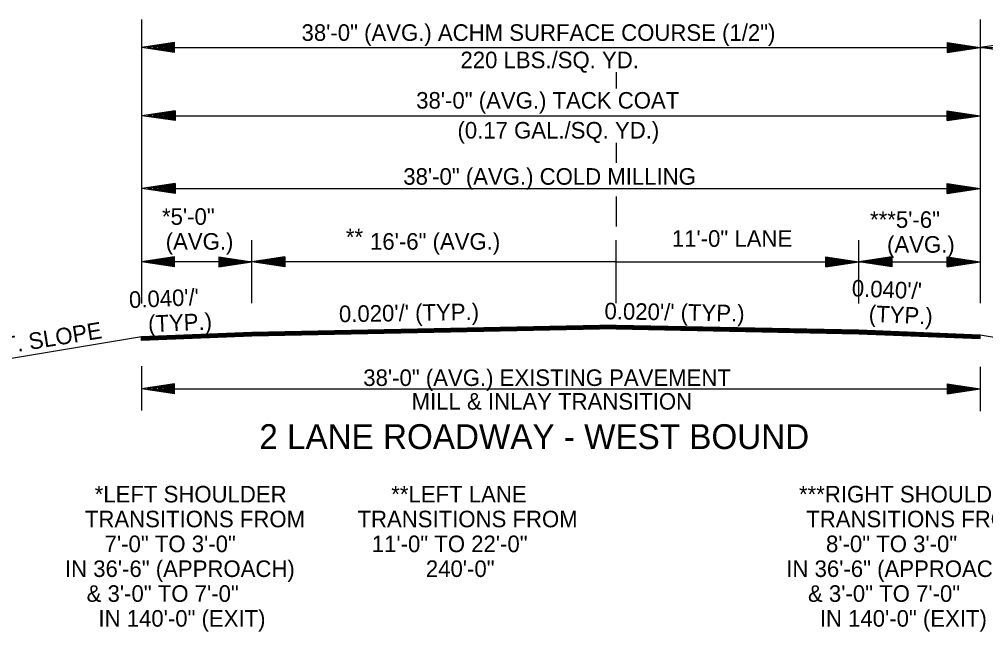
# Model space of a CAD drawing. Extents: x 542112 to 1930787, y -1968972 to 596640.
# Drawn here: x 544342.8 to 544780.6, y -1951874.4 to -1951597.2 of the extents above; entities that cross this region are included whole.
import ezdxf

# ---------------------------------------------------------------- set-up
doc = ezdxf.new("R2010")
doc.units = 0
doc.layers.add('R_Draft', color=7, linetype='Continuous')

msp = doc.modelspace()

# ---------------------------------------------------------------- linework, layer by layer
at = {"layer": 'R_Draft'}
for p, q in [((544398.18, -1951597.18), (544398.18, -1951725.86)), ((544778.18, -1951597.18), (544778.18, -1951725.69)), ((544413.18, -1951607.68), (544398.18, -1951609.93)), ((544413.18, -1951608.06), (544400.68, -1951609.93)), ((544413.18, -1951612.18), (544413.18, -1951607.68)), ((544763.18, -1951607.68), (544778.18, -1951609.93)), ((544763.18, -1951607.68), (544763.18, -1951612.18)), ((544763.18, -1951608.06), (544775.67, -1951609.93)), ((544793.18, -1951607.68), (544778.18, -1951609.93)), ((544793.18, -1951607.68), (544778.18, -1951609.93)), ((544413.18, -1951612.18), (544398.18, -1951609.93)), ((544413.18, -1951611.81), (544400.68, -1951609.93)), ((544413.18, -1951608.44), (544403.26, -1951609.93)), ((544413.18, -1951611.43), (544403.26, -1951609.93)), ((544413.18, -1951608.82), (544405.76, -1951609.93)), ((544413.18, -1951611.05), (544405.76, -1951609.93)), ((544408.18, -1951609.93), (544778.18, -1951609.93)), ((544413.18, -1951609.2), (544408.3, -1951609.93)), ((544413.18, -1951610.66), (544408.3, -1951609.93)), ((544413.18, -1951609.58), (544410.81, -1951609.93)), ((544413.18, -1951610.29), (544410.81, -1951609.93)), ((544763.18, -1951608.44), (544773.09, -1951609.93)), ((544763.18, -1951608.82), (544770.6, -1951609.93)), ((544763.18, -1951609.21), (544768.05, -1951609.93)), ((544763.18, -1951609.58), (544765.55, -1951609.93)), ((544763.18, -1951612.18), (544778.18, -1951609.93)), ((544763.18, -1951610.67), (544768.05, -1951609.93)), ((544763.18, -1951611.43), (544773.09, -1951609.93)), ((544763.18, -1951611.81), (544775.67, -1951609.93)), ((544763.18, -1951611.05), (544770.6, -1951609.93)), ((544763.18, -1951610.29), (544765.55, -1951609.93)), ((544778.18, -1951609.93), (545048.18, -1951609.93)), ((544793.18, -1951612.18), (544778.18, -1951609.93)), ((544793.18, -1951612.18), (544778.18, -1951609.93)), ((544613.18, -1951621.16), (544613.18, -1951628.53)), ((544413.38, -1951638.55), (544398.38, -1951640.8)), ((544413.38, -1951638.93), (544400.88, -1951640.8)), ((544413.38, -1951638.55), (544413.38, -1951643.05)), ((544763.18, -1951638.55), (544778.18, -1951640.8)), ((544763.18, -1951643.05), (544763.18, -1951638.55)), ((544763.18, -1951638.93), (544775.67, -1951640.8)), ((544413.38, -1951643.05), (544398.38, -1951640.8)), ((544413.38, -1951642.68), (544400.88, -1951640.8)), ((544413.38, -1951639.31), (544403.46, -1951640.8)), ((544413.38, -1951642.29), (544403.46, -1951640.8)), ((544413.38, -1951639.68), (544405.96, -1951640.8)), ((544413.38, -1951641.92), (544405.96, -1951640.8)), ((544408.18, -1951640.8), (544778.18, -1951640.8)), ((544413.38, -1951640.07), (544408.5, -1951640.8)), ((544413.38, -1951641.54), (544408.5, -1951640.8)), ((544413.38, -1951640.45), (544411.01, -1951640.8)), ((544413.38, -1951641.15), (544411.01, -1951640.8)), ((544763.18, -1951639.31), (544773.09, -1951640.8)), ((544763.18, -1951639.68), (544770.6, -1951640.8)), ((544763.18, -1951640.07), (544768.05, -1951640.8)), ((544763.18, -1951640.45), (544765.55, -1951640.8)), ((544763.18, -1951643.05), (544778.18, -1951640.8)), ((544763.18, -1951641.53), (544768.05, -1951640.8)), ((544763.18, -1951642.29), (544773.09, -1951640.8)), ((544763.18, -1951642.68), (544775.67, -1951640.8)), ((544763.18, -1951641.92), (544770.6, -1951640.8)), ((544763.18, -1951641.15), (544765.55, -1951640.8)), ((544613.18, -1951653.15), (544613.18, -1951662.11)), ((544413.38, -1951671.48), (544398.38, -1951673.73)), ((544413.38, -1951675.98), (544398.38, -1951673.73)), ((544413.38, -1951671.86), (544400.88, -1951673.73)), ((544413.38, -1951675.61), (544400.88, -1951673.73)), ((544413.38, -1951672.24), (544403.46, -1951673.73)), ((544413.38, -1951675.22), (544403.46, -1951673.73)), ((544413.38, -1951672.61), (544405.96, -1951673.73)), ((544413.38, -1951674.85), (544405.96, -1951673.73)), ((544408.18, -1951673.73), (544778.18, -1951673.73)), ((544413.38, -1951673), (544408.5, -1951673.73)), ((544413.38, -1951674.47), (544408.5, -1951673.73)), ((544413.38, -1951673.38), (544411.01, -1951673.73)), ((544413.38, -1951674.08), (544411.01, -1951673.73)), ((544413.38, -1951671.48), (544413.38, -1951675.98)), ((544763.18, -1951671.48), (544778.18, -1951673.73)), ((544763.18, -1951675.98), (544763.18, -1951671.48)), ((544763.18, -1951671.86), (544775.67, -1951673.73)), ((544763.18, -1951672.24), (544773.09, -1951673.73)), ((544763.18, -1951672.61), (544770.6, -1951673.73)), ((544763.18, -1951673), (544768.05, -1951673.73)), ((544763.18, -1951673.38), (544765.55, -1951673.73)), ((544763.18, -1951675.98), (544778.18, -1951673.73)), ((544763.18, -1951674.46), (544768.05, -1951673.73)), ((544763.18, -1951675.22), (544773.09, -1951673.73)), ((544763.18, -1951675.61), (544775.67, -1951673.73)), ((544763.18, -1951674.85), (544770.6, -1951673.73)), ((544763.18, -1951674.08), (544765.55, -1951673.73)), ((544613.18, -1951677.36), (544613.18, -1951691)), ((544448.18, -1951725.69), (544448.18, -1951697.13)), ((544613.18, -1951725.69), (544613.18, -1951697.13)), ((544723.18, -1951725.86), (544723.18, -1951697.13)), ((544413.18, -1951704.78), (544398.18, -1951707.03)), ((544448.18, -1951707.03), (544398.18, -1951707.03)), ((544413.18, -1951709.28), (544398.18, -1951707.03)), ((544413.18, -1951705.15), (544400.68, -1951707.03)), ((544413.18, -1951708.9), (544400.68, -1951707.03)), ((544413.18, -1951705.53), (544403.26, -1951707.03)), ((544413.18, -1951708.52), (544403.26, -1951707.03)), ((544413.18, -1951705.91), (544405.76, -1951707.03)), ((544413.18, -1951708.14), (544405.76, -1951707.03)), ((544413.18, -1951706.29), (544408.3, -1951707.03)), ((544413.18, -1951707.75), (544408.3, -1951707.03)), ((544413.18, -1951706.67), (544410.81, -1951707.03)), ((544413.18, -1951707.38), (544410.81, -1951707.03)), ((544413.18, -1951709.28), (544413.18, -1951704.78)), ((544433.18, -1951704.78), (544448.18, -1951707.03)), ((544433.18, -1951704.78), (544433.18, -1951709.28)), ((544433.18, -1951705.15), (544445.67, -1951707.03)), ((544433.18, -1951705.53), (544443.09, -1951707.03)), ((544433.18, -1951705.91), (544440.6, -1951707.03)), ((544433.18, -1951706.3), (544438.05, -1951707.03)), ((544433.18, -1951706.67), (544435.55, -1951707.03)), ((544433.18, -1951709.28), (544448.18, -1951707.03)), ((544433.18, -1951707.76), (544438.05, -1951707.03)), ((544433.18, -1951708.52), (544443.09, -1951707.03)), ((544433.18, -1951708.9), (544445.67, -1951707.03)), ((544433.18, -1951708.14), (544440.6, -1951707.03)), ((544433.18, -1951707.38), (544435.55, -1951707.03)), ((544463.18, -1951704.78), (544448.18, -1951707.03)), ((544613.18, -1951707.03), (544448.18, -1951707.03)), ((544463.18, -1951709.28), (544448.18, -1951707.03)), ((544463.18, -1951705.15), (544450.68, -1951707.03)), ((544463.18, -1951708.9), (544450.68, -1951707.03)), ((544463.18, -1951705.53), (544453.26, -1951707.03)), ((544463.18, -1951708.52), (544453.26, -1951707.03)), ((544463.18, -1951705.91), (544455.76, -1951707.03)), ((544463.18, -1951708.14), (544455.76, -1951707.03)), ((544463.18, -1951706.3), (544458.3, -1951707.03)), ((544463.18, -1951707.76), (544458.3, -1951707.03)), ((544463.18, -1951706.67), (544460.81, -1951707.03)), ((544463.18, -1951707.38), (544460.81, -1951707.03)), ((544463.18, -1951704.78), (544463.18, -1951709.28)), ((544613.18, -1951707.03), (544723.18, -1951707.03)), ((544708.18, -1951704.78), (544723.18, -1951707.03)), ((544708.18, -1951709.28), (544708.18, -1951704.78)), ((544708.18, -1951705.15), (544720.67, -1951707.03)), ((544708.18, -1951705.53), (544718.09, -1951707.03)), ((544708.18, -1951705.91), (544715.6, -1951707.03)), ((544708.18, -1951706.29), (544713.05, -1951707.03)), ((544708.18, -1951706.67), (544710.55, -1951707.03)), ((544708.18, -1951709.28), (544723.18, -1951707.03)), ((544708.18, -1951707.75), (544713.05, -1951707.03)), ((544708.18, -1951708.52), (544718.09, -1951707.03)), ((544708.18, -1951708.9), (544720.67, -1951707.03)), ((544708.18, -1951708.14), (544715.6, -1951707.03)), ((544708.18, -1951707.38), (544710.55, -1951707.03)), ((544738.18, -1951704.78), (544723.18, -1951707.03)), ((544723.18, -1951707.03), (544778.18, -1951707.03)), ((544738.18, -1951709.28), (544723.18, -1951707.03)), ((544738.18, -1951705.15), (544725.68, -1951707.03)), ((544738.18, -1951708.9), (544725.68, -1951707.03)), ((544738.18, -1951705.53), (544728.26, -1951707.03)), ((544738.18, -1951708.52), (544728.26, -1951707.03)), ((544738.18, -1951705.91), (544730.76, -1951707.03)), ((544738.18, -1951708.14), (544730.76, -1951707.03)), ((544738.18, -1951706.3), (544733.3, -1951707.03)), ((544738.18, -1951707.76), (544733.3, -1951707.03)), ((544738.18, -1951706.67), (544735.81, -1951707.03)), ((544738.18, -1951707.38), (544735.81, -1951707.03)), ((544738.18, -1951704.78), (544738.18, -1951709.28)), ((544763.18, -1951704.78), (544778.18, -1951707.03)), ((544763.18, -1951709.28), (544763.18, -1951704.78)), ((544763.18, -1951705.15), (544775.67, -1951707.03)), ((544763.18, -1951705.53), (544773.09, -1951707.03)), ((544763.18, -1951705.91), (544770.6, -1951707.03)), ((544763.18, -1951706.29), (544768.05, -1951707.03)), ((544763.18, -1951706.67), (544765.55, -1951707.03)), ((544763.18, -1951709.28), (544778.18, -1951707.03)), ((544763.18, -1951707.75), (544768.05, -1951707.03)), ((544763.18, -1951708.52), (544773.09, -1951707.03)), ((544763.18, -1951708.9), (544775.67, -1951707.03)), ((544763.18, -1951708.14), (544770.6, -1951707.03)), ((544763.18, -1951707.38), (544765.55, -1951707.03)), ((544448.18, -1951738.93), (544398.18, -1951740.93)), ((544448.18, -1951739.23), (544398.18, -1951741.23)), ((544448.18, -1951739.53), (544398.18, -1951741.53)), ((544613.18, -1951735.63), (544448.18, -1951738.93)), ((544613.18, -1951735.93), (544448.18, -1951739.23)), ((544613.18, -1951736.23), (544448.18, -1951739.53)), ((544613.18, -1951736.53), (544448.18, -1951739.83)), ((544613.18, -1951736.83), (544448.18, -1951740.13)), ((544613.18, -1951737.13), (544448.18, -1951740.43)), ((544613.18, -1951737.3), (544448.18, -1951740.6)), ((544613.18, -1951735.63), (544723.18, -1951737.83)), ((544613.18, -1951735.93), (544723.18, -1951738.13)), ((544613.18, -1951736.23), (544723.18, -1951738.43)), ((544613.18, -1951736.53), (544723.18, -1951738.73)), ((544613.18, -1951736.83), (544723.18, -1951739.03)), ((544613.18, -1951737.13), (544723.18, -1951739.33)), ((544613.18, -1951737.3), (544723.18, -1951739.5)), ((544723.18, -1951737.83), (544778.18, -1951740.03)), ((544723.18, -1951738.13), (544778.18, -1951740.33)), ((544723.18, -1951738.43), (544778.18, -1951740.63)), ((544723.18, -1951738.73), (544778.18, -1951740.93)), ((544723.18, -1951739.03), (544778.18, -1951741.23)), ((544723.18, -1951739.33), (544778.18, -1951741.53)), ((544723.18, -1951739.5), (544778.18, -1951741.7)), ((544398.18, -1951740.93), (544294.5, -1951758.21)), ((544448.18, -1951739.83), (544398.18, -1951741.83)), ((544448.18, -1951740.13), (544398.18, -1951742.13)), ((544448.18, -1951740.43), (544398.18, -1951742.43)), ((544448.18, -1951740.6), (544398.18, -1951742.6)), ((544398.18, -1951742.6), (544398.18, -1951740.93)), ((544778.18, -1951740.03), (544913.18, -1951762.53)), ((544778.18, -1951741.7), (544778.18, -1951740.03)), ((544398.18, -1951754.24), (544398.18, -1951774.24)), ((544778.18, -1951754.57), (544778.18, -1951774.57)), ((544413.17, -1951762.24), (544398.17, -1951764.49)), ((544413.17, -1951766.74), (544398.17, -1951764.49)), ((544413.17, -1951762.62), (544400.67, -1951764.49)), ((544413.17, -1951766.37), (544400.67, -1951764.49)), ((544413.17, -1951763), (544403.25, -1951764.49)), ((544413.17, -1951765.98), (544403.25, -1951764.49)), ((544413.17, -1951763.37), (544405.75, -1951764.49)), ((544413.17, -1951765.61), (544405.75, -1951764.49)), ((544408.18, -1951764.49), (544778.18, -1951764.49)), ((544413.17, -1951763.76), (544408.29, -1951764.49)), ((544413.17, -1951765.22), (544408.29, -1951764.49)), ((544413.17, -1951764.14), (544410.8, -1951764.49)), ((544413.17, -1951764.84), (544410.8, -1951764.49)), ((544413.17, -1951766.74), (544413.17, -1951762.24)), ((544763.18, -1951762.24), (544778.18, -1951764.49)), ((544763.18, -1951762.24), (544763.18, -1951766.74)), ((544763.18, -1951762.62), (544775.67, -1951764.49)), ((544763.18, -1951763), (544773.09, -1951764.49)), ((544763.18, -1951763.37), (544770.6, -1951764.49)), ((544763.18, -1951763.76), (544768.05, -1951764.49)), ((544763.18, -1951764.14), (544765.55, -1951764.49)), ((544763.18, -1951766.74), (544778.18, -1951764.49)), ((544763.18, -1951765.23), (544768.05, -1951764.49)), ((544763.18, -1951765.98), (544773.09, -1951764.49)), ((544763.18, -1951766.37), (544775.67, -1951764.49)), ((544763.18, -1951765.61), (544770.6, -1951764.49)), ((544763.18, -1951764.84), (544765.55, -1951764.49))]:
    msp.add_line(p, q, dxfattribs=at)

# ---------------------------------------------------------------- texts
for s, height, p in [('38\'-0" (AVG.) ACHM SURFACE COURSE (1/2")', 7.5, (544470.7, -1951606.92)), ('220 LBS./SQ. YD. ', 7.5, (544542.69, -1951619.31)), ('38\'-0" (AVG.) TACK COAT', 7.5, (544522.64, -1951637.6)), ('(0.17 GAL./SQ. YD.)', 7.5, (544541.33, -1951651.14)), ('38\'-0" (AVG.) COLD MILLING', 7.5, (544516.79, -1951672.06)), ('*5\'-0"', 7.5, (544407.47, -1951690.22)), ('***5\'-6"', 7.5, (544728.24, -1951691.59)), ('(AVG.)', 7.5, (544409.16, -1951701.47)), ('**', 7.5, (544490.77, -1951699.5)), ('16\'-6" (AVG.)', 7.5, (544501.72, -1951701.47)), ('11\'-0" LANE', 7.5, (544638.45, -1951700.16)), ('(AVG.)', 7.5, (544735.94, -1951702.84)), ('38\'-0" (AVG.) EXISTING PAVEMENT', 7.5, (544498.66, -1951763.17)), ('MILL & INLAY TRANSITION', 7.5, (544520.57, -1951773.89)), ('2 LANE ROADWAY - WEST BOUND', 11.25, (544451.58, -1951791.73)), ('*LEFT SHOULDER', 7.5, (544377, -1951815.91)), ('**LEFT LANE', 7.5, (544511.34, -1951815.91)), ('***RIGHT SHOULDER', 7.5, (544696.05, -1951815.91)), ('TRANSITIONS FROM ', 7.5, (544372.54, -1951827.16)), ('TRANSITIONS FROM ', 7.5, (544496.04, -1951827.16)), ('TRANSITIONS FROM ', 7.5, (544699.33, -1951827.16)), ('7\'-0" TO 3\'-0"', 7.5, (544381.49, -1951838.41)), ('11\'-0" TO 22\'-0"', 7.5, (544502.51, -1951838.41)), ('8\'-0" TO 3\'-0"', 7.5, (544708.28, -1951838.41)), ('IN 36\'-6" (APPROACH)', 7.5, (544363.51, -1951849.66)), ('240\'-0"', 7.5, (544527.02, -1951849.66)), ('IN 36\'-6" (APPROACH)', 7.5, (544690.3, -1951849.66)), ('& 3\'-0" TO 7\'-0"', 7.5, (544373.34, -1951860.91)), ('& 3\'-0" TO 7\'-0"', 7.5, (544700.13, -1951860.91)), ('IN 140\'-0" (EXIT)', 7.5, (544378.68, -1951872.16)), ('IN 140\'-0" (EXIT)', 7.5, (544705.47, -1951872.16))]:
    msp.add_text(s, height=height, dxfattribs=at).set_placement(p)
for s, rotation, p in [("  0.040'/'", 357.552, (544714.28, -1951722.32)), ("  0.040'/'", 2.448, (544387.12, -1951728.16)), ("0.020'/' (TYP.)", 0.9719, (544487.7, -1951734.33)), ("0.020'/' (TYP.)", 359.0281, (544607.88, -1951732.96)), (' (TYP.)', 357.552, (544724.75, -1951734.02)), (' (TYP.)', 2.448, (544398.54, -1951738.93)), ('EXIST. SLOPE', 9.1534, (544313.57, -1951752.32))]:
    msp.add_text(s, height=7.5, rotation=rotation, dxfattribs=at).set_placement(p)

doc.saveas('drawing.dxf')
